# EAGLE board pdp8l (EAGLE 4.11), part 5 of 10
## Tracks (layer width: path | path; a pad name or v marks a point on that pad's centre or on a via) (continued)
MA05\  (via drill 0.61) (continued)
  Route15 0.203: v402.74,227.43 403.15,227.43 410.06,220.52 410.06,209.14 411.68,207.52 412.09,207.52 414.93,204.67 418.19,204.67 430.38,192.48 432,192.48 432.82,191.67 437.29,191.67 444.6,184.35 448.67,184.35 B01.H2 | v91.85,261.16 91.85,259.94 115.01,236.78 120.7,236.78 121.11,236.37 121.92,236.37 140.61,217.68 145.49,217.68 162.15,201.02 162.97,201.02 165.81,198.17 166.62,198.17 169.47,195.33 170.69,195.33 172.31,193.7 B23.D1 | v224.33,190.04 221.08,186.79 v222.71,185.17 | v366.57,276.2 397.87,244.91 401.12,244.91 AB05.AL1
  Bottom 0.203: v91.85,261.16 91.44,261.57 48.77,261.57 46.33,259.13 18.69,259.13 17.88,259.94 A35.E2 | v224.33,190.04 226.37,192.07 265.38,192.07 268.22,189.23 282.85,189.23 283.67,190.04 B14.E2 | v222.71,185.17 222.3,185.57 189.38,185.57 185.72,189.23 v173.53,189.23 | v366.57,276.2 366.17,276.61 357.23,276.61 356.41,277.42 334.87,277.42 333.25,275.79 317.4,275.79 316.99,275.39 306.02,275.39 304.39,277.01 286.92,277.01 286.51,276.61 255.63,276.61 254.81,277.42 242.21,277.42 v241.81,277.01
MA06  (via drill 0.61)
  Top 0.203: v219.46,122.58 216.21,125.83 v216.21,165.25 | v247.5,200.61 250.34,203.45 250.34,216.05 247.9,218.49 247.9,222.15 250.75,224.99 v250.75,257.91 | v321.87,268.88 323.49,270.51 323.49,274.57 v327.96,279.04 | v388.93,281.89 391.77,279.04 391.77,277.83 392.58,277.01 412.9,277.01 412.9,260.76 415.75,257.91 415.75,247.75 411.28,243.28 411.28,242.06 AB04.AM2
  Route2 0.203: v216.21,165.25 216.61,165.25 228.4,177.04 228.4,181.51 v247.5,200.61 | v314.15,261.16 v321.87,268.88 | v327.96,279.04 329.18,279.04 332.44,275.79 334.06,275.79 335.28,277.01 367.79,277.01 368.2,277.42 371.04,277.42 371.86,278.23 375.51,278.23 376.33,279.04 386.08,279.04 v388.93,281.89
  Bottom 0.203: v219.46,122.58 232.05,122.58 232.87,123.39 C18.E2 | v250.75,257.91 251.56,258.72 311.71,258.72 v314.15,261.16
MA06\  (via drill 0.61)
  Top 0.203: v412.09,172.97 412.5,173.38 412.5,205.89 410.06,208.33 410.06,212.8 410.46,213.21 410.46,214.83 412.09,214.83 415.75,218.49 415.75,239.62 416.97,240.84 AB04.AM1 | v219.05,172.97 219.05,126.24 220.68,124.61 C19.E2 | v282.85,172.57 282.85,185.17 281.23,186.79 B14.F2
  Route15 0.203: v64.21,279.04 104.85,238.4 105.26,238.4 113.79,229.87 113.79,229.46 114.2,229.06 115.01,229.06 151.18,192.89 151.18,192.07 167.84,175.41 167.84,173.79 169.47,172.16 B23.M2
  Bottom 0.203: B01.M2 448.67,171.75 447.45,172.97 v412.09,172.97 411.68,172.97 375.92,172.97 375.51,173.38 341.78,173.38 341.38,172.97 282.85,172.97 v282.85,172.57 282.45,172.97 219.46,172.97 v219.05,172.97 171.09,172.97 170.28,172.16 B23.M2 | v64.21,279.04 3.25,279.04 3.25,259.94 7.32,255.88 15.04,255.88 16.66,254.25 A35.H2
MA07  (via drill 0.61)
  Top 0.203: v360.88,244.91 358.44,247.34 358.44,260.35 355.19,263.6 355.19,270.1 352.35,272.95 v352.35,273.36 | v212.14,147.37 210.51,145.75 210.51,135.99 209.7,135.18 209.7,132.74 213.77,128.68 215.8,128.68 215.8,125.02 220.27,120.55 220.27,118.11 C19.H2
  Route2 0.203: v360.88,244.91 360.88,245.31 371.45,255.88 376.73,255.88 379.17,258.32 387.3,258.32 391.77,262.79 407.62,246.94 407.62,244.91 AB04.AL2 | v352.35,273.36 351.13,274.57 348.29,271.73 342.19,271.73 332.84,262.38 327.15,262.38 303.58,238.81 303.58,238.4 294.64,229.46 294.23,229.46 293.42,228.65 292.61,228.65 289.76,225.81 289.36,225.81 288.95,225.4 288.95,224.59 283.67,219.3 283.67,218.49 250.34,185.17 249.94,185.17 v212.14,147.37
  Bottom 0.203: C19.H2 221.08,116.89 221.89,116.08 232.05,116.08 232.87,116.89 C18.H2
MA07\  (via drill 0.61)
  Top 0.203: v287.32,273.76 279.6,266.04 279.6,262.38 279.2,261.98 279.2,257.1 278.38,256.29 278.38,255.47 279.2,254.66 279.2,230.28 v278.79,229.87
  Route15 0.203: B01.P2 449.48,165.66 449.48,169.72 451.1,171.35 451.1,186.38 444.6,192.89 444.6,205.89 425.91,224.59 425.91,230.28 422.66,233.53 422.66,234.34 416.15,240.84 416.15,242.06 414.53,243.69 AB04.AL1 413.71,244.91 411.28,244.91 387.3,268.88 385.67,268.88 383.24,271.32 378.76,271.32 372.26,277.83 371.45,277.83 369.01,275.39 v369.42,274.98 | A35.K2 17.88,248.16 17.88,252.22 23.98,258.32 19.51,262.79 19.51,270.92 33.33,284.73 60.96,284.73 169.06,176.63 170.69,176.63 172.31,175.01 B23.L1 | v278.79,229.87 278.79,229.46 279.2,229.06 279.2,218.08 293.83,203.45 293.83,201.83 295.05,200.61 295.05,196.14 v297.89,193.29
  Bottom 0.203: B23.L1 173.53,175.01 174.35,175.82 189.79,175.82 193.45,179.48 256.03,179.48 259.28,182.73 278.38,182.73 278.79,183.13 283.26,183.13 283.67,183.54 B14.H2 284.89,184.35 288.54,184.35 288.54,190.45 290.17,192.07 296.67,192.07 v297.89,193.29 | v369.42,274.98 369.01,275.39 365.76,275.39 364.95,276.2 356.82,276.2 356.01,277.01 335.28,277.01 333.65,275.39 317.81,275.39 317.4,274.98 288.54,274.98 v287.32,273.76
MA08  (via drill 0.61)
  Top 0.203: v314.55,278.23 314.55,265.23 313.33,264.01 A12.D1 | v423.06,276.2 422.66,275.79 422.66,242.88 423.47,242.06 AB03.AM2 | v202.39,119.33 202.79,119.74 202.79,179.88 201.98,180.7 201.98,182.32 203.2,183.54 v203.2,221.74
  Route2 0.203: v230.84,227.03 233.68,227.03 267.41,260.76 v267.41,261.16
  Bottom 0.203: C18.F2 229.62,120.14 228.8,119.33 219.46,119.33 218.24,120.55 C19.F2 217.02,120.14 216.21,119.33 v202.39,119.33 | v314.55,278.23 330.81,278.23 332.44,279.86 358.85,279.86 359.66,279.04 364.95,279.04 366.17,280.26 384.86,280.26 386.89,278.23 391.36,278.23 392.18,279.04 420.22,279.04 v423.06,276.2 | v203.2,221.74 203.2,227.03 v230.84,227.03 | v267.41,261.16 267.82,261.57 289.76,261.57 293.42,265.23 310.9,265.23 312.12,264.01 A12.D1
MA08\  (via drill 0.61)
  Top 0.203: v434.44,157.53 434.85,157.94 434.85,201.02 432.41,203.45 432.41,218.08 432,218.49 432,239.62 430.78,240.84 AB03.AM1
  Bottom 0.203: A35.M2 17.88,241.66 18.69,242.47 425.91,242.47 426.72,241.66 429.56,241.66 AB03.AM1 | v434.44,157.53 443.79,157.53 445.41,155.91 B01.T2
MA09  (via drill 0.61)
  Top 0.203: v185.32,55.12 190.19,55.12 190.19,213.21 v189.79,213.61
  Route2 0.203: v189.79,213.61 253.59,277.42 260.91,277.42 v264.57,281.08 | v362.92,259.54 363.73,259.54 378.76,274.57 382.42,274.57 v385.27,277.42
  Route15 0.203: v264.57,281.08 267.82,284.33 338.53,284.33 349.91,272.95 349.91,272.54 351.13,271.32 351.54,271.32 362.92,259.94 v362.92,259.54 | v385.27,277.42 385.67,277.42 391.36,271.73 391.77,271.73 392.18,271.32 392.18,270.92 416.97,246.13 419,246.13 420.22,244.91 AB03.AL2
  Bottom 0.203: v185.32,55.12 158.5,55.12 157.68,54.3 D24.E2
MA09\  (via drill 0.61)
  Top 0.203: v24.79,210.77 25.2,211.18 25.2,237.19 v23.57,238.81 | v177.6,12.45 171.91,18.14 171.91,60 170.28,61.62 168.66,61.62 168.66,55.52 169.47,54.71 D23.E2
  Route2 0.203: v23.57,238.81 23.16,238.81 21.13,236.78 19.1,236.78 17.88,235.56 A35.P2 | v358.85,12.45 359.26,12.85 361.7,12.85 403.96,55.12 405.59,55.12 406.81,56.34 406.81,57.96 414.12,65.28 418.19,65.28 420.22,67.31 420.22,69.75 429.56,79.1 429.56,80.72 433.22,84.38 433.22,86.41 451.1,104.29 451.1,114.86 455.17,118.92 455.17,123.39 C01.E1
  Route15 0.203: C01.E1 455.57,124.61 455.57,128.27 454.36,129.49 454.36,215.24 428.75,240.84 428.75,242.06 427.13,243.69 AB03.AL1 | v24.79,210.77 32.11,203.45 32.11,192.89 86.97,138.02 87.78,138.02 169.47,56.34 169.47,54.71 D23.E2 | v358.85,12.45 352.35,5.94 342.6,5.94 341.38,7.16 322.27,7.16 v314.15,15.29
  Bottom 0.203: v314.15,15.29 312.12,17.32 307.64,17.32 307.24,16.92 305.61,16.92 305.21,17.32 295.86,17.32 292.61,14.07 233.68,14.07 230.02,10.41 179.63,10.41 v177.6,12.45
MA10  (via drill 0.61)
  Top 0.203: v374.7,277.42 368.2,283.92 308.86,283.92 308.86,281.08 v303.99,276.2 | v167.84,210.77 168.25,210.36 168.25,124.21 162.15,118.11 162.15,79.1 164.59,76.66 164.59,69.75 158.5,63.65 158.5,49.02 157.68,48.21 D24.H2
  Route2 0.203: v277.98,275.39 274.32,279.04 273.91,278.64 264.97,278.64 262.53,276.2 259.69,276.2 216.21,232.72 216.21,230.68 215.8,230.28 213.77,230.28 203.2,219.71 203.2,219.3 202.79,218.9 200.35,218.9 199.14,217.68 196.29,217.68 194.67,216.05 193.85,216.05 v192.23,214.43
  Route15 0.203: v374.7,277.42 376.73,279.45 383.64,279.45 384.45,278.64 387.71,278.64 391.36,274.98 399.49,274.98 399.9,274.57 405.59,274.57 436.47,243.69 436.47,242.06 AB02.AM2
  Bottom 0.203: D24.H2 157.68,48.21 158.5,49.02 167.84,49.02 169.06,47.8 D23.H2 | v303.99,276.2 303.17,275.39 v277.98,275.39 | v192.23,214.43 188.57,210.77 v167.84,210.77
MA10\  (via drill 0.61)
  Top 0.203: v434.44,121.77 432.82,123.39 432.82,125.42 431.6,126.64 431.6,215.65 429.56,217.68 429.56,220.93 428.35,222.15 428.35,241.25 v427.13,242.47 | v74.37,283.92 30.07,283.92 26.01,279.86 26.01,272.54 18.69,265.23 18.69,229.87 17.88,229.06 A35.S2 | v254.41,268.88 254.41,274.57 261.72,281.89 261.72,283.11 281.23,283.11 281.23,279.86 281.63,279.45 294.23,279.45 v294.23,273.76 | v382.02,253.44 387.3,248.16 v387.3,244.91
  Route2 0.203: v74.37,283.92 105.66,283.92 106.88,282.7 107.7,283.52 165.41,283.52 v167.44,281.48 | v346.66,232.72 348.69,232.72 352.75,236.78 360.07,236.78 375.51,252.22 380.8,252.22 v382.02,253.44
  Route15 0.203: v167.44,281.48 235.71,281.48 245.47,271.73 251.56,271.73 v254.41,268.88 | v294.23,273.76 299.52,268.48 303.99,268.48 324.31,248.16 325.53,248.16 325.93,247.75 326.75,247.75 328.37,249.38 328.78,248.97 329.18,248.97 330,248.16 330,247.75 330.4,247.34 331.62,247.34 343.41,235.56 344.22,235.56 346.66,233.12 v346.66,232.72
  Bottom 0.203: v434.44,121.77 435.66,121.77 441.76,115.67 451.1,115.67 451.92,114.86 C01.J1 | AB02.AM1 442.16,241.66 441.35,242.47 v427.13,242.47 427.13,242.88 401.12,242.88 398.27,245.72 388.11,245.72 v387.3,244.91
MA11  (via drill 0.61)
  Top 0.203: v377.14,278.23 374.7,278.23 368.61,284.33 293.83,284.33 293.83,281.08 293.01,280.26 281.63,280.26 281.63,283.52 257.66,283.52 257.66,278.64 254.81,275.79 253.19,275.79 253.19,282.3 251.97,283.52 230.84,283.52 v230.84,278.64 | v222.71,279.04 183.69,279.04 183.69,253.03 180.85,250.19 180.85,185.98 180.44,185.57 180.44,181.91 180.85,181.51 180.85,130.3 171.5,120.95 171.5,65.28 167.84,61.62 167.84,52.27 167.03,51.46 D23.F2
  Route15 0.203: v377.14,278.23 377.55,278.64 383.64,278.64 384.05,278.23 385.67,278.23 389.33,274.57 399.08,274.57 400.71,272.95 402.74,272.95 430.78,244.91 432.82,244.91 AB02.AL2
  Bottom 0.203: D24.F2 154.43,51.46 155.25,52.27 165.41,52.27 166.22,51.46 D23.F2 | v230.84,278.64 230.02,279.45 223.11,279.45 v222.71,279.04
MA11\  (via drill 0.61)
  Top 0.203: v61.77,264.41 63.4,266.04 63.4,270.92 71.12,278.64 v103.63,278.64 | v426.72,272.54 438.51,260.76 438.51,245.72 | 438.51,245.72 439.32,244.91 AB02.AL1 | v438.1,200.61 438.51,201.02 438.51,245.72
  Route2 0.203: v61.77,264.41 44.7,247.34 44.7,246.53 21.13,222.96 17.88,222.96 A35.U2 | v277.17,263.2 277.98,263.2 289.76,274.98 292.61,274.98 293.01,275.39 299.11,275.39 306.02,282.3 306.83,282.3 307.24,281.89 307.24,281.08 312.93,275.39 v317.81,280.26 | v326.75,279.45 327.15,279.45 327.56,279.86 385.67,279.86 388.52,282.7 390.96,282.7 401.52,272.14 401.52,271.73 401.93,271.32 425.5,271.32 v426.72,272.54 | v438.1,200.61 437.29,199.8 453.95,183.13 453.95,148.59 452.32,146.96 452.32,141.68 451.51,140.87 451.51,140.06 451.1,139.65 451.1,116.48 450.7,116.08 450.7,110.39 446.23,105.92 446.23,102.26 C01.N2
  Route15 0.203: v103.63,278.64 113.39,278.64 118.67,283.92 245.87,283.92 258.06,271.73 268.63,271.73 v277.17,263.2
  Bottom 0.203: v317.81,280.26 318.21,280.67 325.53,280.67 v326.75,279.45
MA_ENABLE(0-4)  (via drill 0.61)
  Top 0.203: AB07.BP1 379.98,164.85 382.02,162.81 382.02,162.41 AB06.BR2 | v392.58,243.69 392.99,243.28 392.99,242.47 393.39,242.06 393.39,166.47 392.58,165.66 AB06.BP1
  Route15 0.203: v359.66,244.91 357.63,246.94 357.63,250.19 A08.J2
  Bottom 0.203: AB07.BR2 370.64,162 371.86,163.22 377.55,163.22 378.36,162.41 382.02,162.41 AB06.BR2 | 390.14,166.47 391.36,165.25 AB06.BP1 | 390.14,166.47 382.42,166.47 381.2,165.25 379.98,165.25 AB07.BP1 | 390.14,166.47 399.08,166.47 400.3,165.25 404.37,165.25 AB05.BP1 | v359.66,244.91 361.29,243.28 392.18,243.28 v392.58,243.69
MA_ENABLE(5-11)  (via drill 0.61)
  Top 0.203: AB03.BR2 420.22,162.41 418.19,164.44 418.19,164.85 AB04.BP1 | v346.25,244.5 346.25,248.56 344.63,250.19 A09.J2 | v393.8,243.28 393.8,163.22 394.61,162.41 AB05.BR2
  Bottom 0.203: AB02.BP1 442.16,165.25 440.94,166.47 431.6,166.47 430.78,165.66 AB03.BP1 429.56,165.25 428.35,166.47 419.4,166.47 418.19,165.25 AB04.BP1 | AB02.BR2 432.82,162.41 432,163.22 422.66,163.22 421.44,162 AB03.BR2 420.22,161.59 419.4,160.78 406.4,160.78 | 406.4,160.78 396.65,160.78 395.83,161.59 AB05.BR2 | 406.4,160.78 407.21,161.59 AB04.BR2 | v346.25,244.5 347.88,242.88 393.39,242.88 v393.8,243.28
MA_LOAD  (via drill 0.61)
  Top 0.203: v366.98,176.22 368.2,175.01 368.2,160.78 366.98,159.56 B08.S1 | v390.14,203.86 390.14,220.52 387.71,222.96 387.71,232.72 390.55,235.56 390.55,245.72 391.77,246.94 AB06.AK1
  Route2 0.203: v366.98,176.22 367.39,176.22 390.14,198.98 v390.14,203.86
  Bottom 0.203: AB02.AK1 442.16,247.75 440.94,248.97 431.6,248.97 430.78,248.16 AB03.AK1 429.56,248.16 428.75,248.97 422.25,248.97 421.03,247.75 418.19,247.75 AB04.AK1 416.97,248.16 416.15,248.97 403.56,248.97 | 390.14,248.97 380.8,248.97 379.98,248.16 AB07.AK1 | 390.14,248.97 391.36,247.75 AB06.AK1 | 403.56,248.97 404.37,248.16 AB05.AK1 | 390.14,248.97 403.56,248.97
MANUAL_PRESET\  (via drill 0.61)
  Top 0.203: v386.89,112.42 387.3,112.01 387.3,87.63 386.08,86.41 C06.U2 | v416.15,114.05 416.15,124.61 414.53,126.24 C04.D1 | v334.06,52.68 336.09,50.65 336.09,42.11 335.69,41.71 D10.K2 | B11.K1 328.37,177.04 328.37,174.6 327.15,173.38 327.15,170.94 330,168.1 330,151.03 v329.18,150.22 328.78,150.22 328.78,146.15 330,144.93 330,129.49 329.59,129.08 329.59,125.42 330,125.02 330,122.58 | 330,122.58 330,96.98 327.15,94.13 327.15,85.19 327.96,84.38 327.96,73.81 330,71.78 330,55.93 328.78,54.71 D11.E1 | v329.59,122.58 330,122.58
  Route2 0.203: B08.E1 366.17,190.04 361.7,190.04 355.19,183.54 355.19,183.13 348.29,176.22 347.88,176.22 341.78,170.13 337.72,170.13 327.15,159.56 327.15,158.34 326.75,157.94 325.93,157.94 324.31,156.31 324.31,154.69 322.68,153.06 B11.U2
  Route15 0.203: v351.94,123.39 360.07,115.27 360.07,111.61 C08.K2
  Bottom 0.203: 386.89,112.83 399.49,112.83 399.9,112.42 409.25,112.42 410.46,111.2 C04.K2 411.68,111.61 413.71,111.61 v416.15,114.05 | 386.89,112.83 377.55,112.83 377.14,112.42 361.7,112.42 360.88,111.61 C08.K2 | 386.89,112.83 v386.89,112.42 | v334.06,52.68 333.65,53.09 329.59,53.09 329.18,53.49 D11.E1 | v329.18,150.22 328.78,150.62 323.9,150.62 322.68,151.84 B11.U2 | v351.94,123.39 349.1,123.39 348.29,122.58 v329.59,122.58
MB00  (via drill 0.61)
  Top 0.203: v277.98,220.52 v277.98,205.08
  Route2 0.203: v229.62,190.86 214.58,175.82 214.58,173.38 214.17,172.97 213.77,172.97 178,137.21 178,135.59 123.95,81.53 123.95,80.72 112.98,69.75 112.98,67.31 D28.A1 | v308.46,251 308.46,250.6 293.83,235.97 293.83,234.75 288.54,229.46 286.92,229.46 v277.98,220.52 | v277.98,205.08 277.57,205.08 267,194.51 267,192.89 265.38,191.26 B16.E1
  Route15 0.203: v340.97,251.82 366.98,225.81 369.42,225.81 AB07.AT2
  Bottom 0.203: v229.62,190.86 230.43,191.67 263.75,191.67 264.57,190.86 B16.E1 | v340.97,251.82 340.56,252.22 311.3,252.22 310.08,251 v308.46,251
MB00\  (via drill 0.61)
  Top 0.203: v373.48,188.82 374.29,189.64 374.29,205.49 372.26,207.52 372.26,221.34 372.67,221.74 AB07.AU2
  Route2 0.203: v386.08,186.38 402.34,202.64 402.34,205.49 412.09,215.24 412.9,215.24 414.12,216.46 415.34,216.46 426.72,227.84 427.53,227.84 445.41,245.72 447.04,245.72 448.67,247.34 A01.K2 | v373.07,227.03 373.07,222.96 AB07.AU2 | v310.49,252.63 310.49,251.82 295.05,236.37 295.05,235.56 294.23,234.75 294.23,234.34 282.85,222.96 282.85,218.9 281.63,217.68 280.01,217.68 265.79,203.45 B16.A1
  Route15 0.203: B16.A1 264.57,203.45 262.53,203.45 228.4,237.59 225.96,237.59 220.27,231.9 218.64,233.53 211.33,233.53 199.14,245.72 193.85,245.72 177.6,261.98 176.38,261.98 173.53,264.82 168.66,264.82 167.44,263.6 A23.D2 | v373.07,227.03 372.67,227.03 v347.88,251.82
  Bottom 0.203: v373.48,188.82 373.48,186.79 374.7,186.79 375.51,185.98 385.67,185.98 v386.08,186.38 | v347.88,251.82 347.47,252.22 341.78,252.22 341.38,252.63 v310.49,252.63
MB01  (via drill 0.61)
  Route2 0.203: v245.87,186.79 197.1,138.02 194.67,138.02 179.22,122.58 178.41,122.58 174.75,118.92 168.66,118.92 119.89,70.16 118.67,70.16 112.57,64.06 110.13,64.06 D28.B1 | v361.7,227.43 360.88,227.43 357.63,224.18 353.97,224.18 351.94,222.15 v351.94,221.74 | v340.16,223.37 340.16,222.96 336.91,219.71 336.91,218.08 v329.18,210.36 | v309.27,227.03 309.27,226.62 304.39,221.74 304.39,221.34 300.74,217.68 295.45,217.68 v265.79,188.01
  Route15 0.203: v329.18,210.36 328.37,211.18 326.34,211.18 324.31,213.21 323.09,213.21 v309.27,227.03
  Bottom 0.203: v245.87,186.79 247.9,188.82 260.1,188.82 261.31,187.6 B16.F1 262.53,187.6 265.38,187.6 v265.79,188.01 | v361.7,227.43 367.39,227.43 367.79,227.84 371.86,227.84 372.26,228.24 AB07.AS2 | v351.94,221.74 350.72,222.96 349.1,222.96 348.29,223.77 340.56,223.77 v340.16,223.37
MB01\  (via drill 0.61)
  Top 0.203: v378.76,232.72 379.58,231.9 379.58,229.06 AB07.AS1 | v416.15,277.01 416.15,253.44 420.62,248.97 v420.62,248.56 | v171.91,280.26 171.91,264.82 172.72,264.01 A23.D1
  Route2 0.203: v408.84,236.78 409.25,236.78 420.62,248.16 v420.62,248.56
  Route15 0.203: B16.B1 261.72,200.61 261.72,203.45 252.37,212.8 251.16,212.8 243.43,220.52 238.56,220.52 237.74,221.34 236.12,221.34 233.68,223.77 227.58,223.77 218.24,233.12 205.64,233.12 177.19,261.57 175.16,261.57 173.53,263.2 A23.D1
  Bottom 0.203: v378.76,232.72 379.58,233.53 382.42,233.53 385.27,236.37 390.55,236.37 390.96,236.78 400.3,236.78 400.71,236.37 403.15,236.37 403.56,236.78 v408.84,236.78 | v420.62,248.56 421.44,249.38 449.07,249.38 453.14,253.44 455.17,253.44 A01.H1 | v416.15,277.01 415.34,277.83 393.39,277.83 392.99,277.42 386.49,277.42 384.05,279.86 366.57,279.86 365.35,278.64 359.26,278.64 358.44,279.45 332.84,279.45 331.22,277.83 315.37,277.83 314.96,277.42 313.74,277.42 311.71,279.45 273.91,279.45 273.51,279.04 238.15,279.04 236.53,280.67 172.31,280.67 v171.91,280.26
MB02  (via drill 0.61)
  Top 0.203: v378.36,250.6 380.8,248.16 380.8,238 382.02,236.78 382.02,234.75 381.2,233.93 381.2,231.09 381.61,230.68 381.61,227.03 382.42,226.21 AB06.AT2 | v368.61,276.61 v368.61,260.35 | v235.31,278.23 235.31,266.85 237.74,264.41 237.74,220.93 v237.34,220.52
  Route2 0.203: D28.F1 110.13,51.05 113.39,51.05 141.83,79.5 159.31,79.5 215.8,135.99 215.8,138.43 252.78,175.41 252.78,175.82 253.19,176.22 255.63,176.22 257.25,177.85 257.25,178.26 261.31,182.32 263.35,182.32 264.57,183.54 B16.H1
  Route15 0.203: v368.61,260.35 v378.36,250.6 | v237.34,220.52 237.74,220.12 237.74,213.21 246.28,204.67 246.69,204.67 264.16,187.2 264.16,186.79 264.57,186.38 264.57,184.76 B16.H1
  Bottom 0.203: v368.61,276.61 367.79,277.42 358.04,277.42 357.23,278.23 334.06,278.23 332.44,276.61 316.59,276.61 316.18,276.2 310.49,276.2 308.46,278.23 286.51,278.23 285.7,277.42 256.44,277.42 255.63,278.23 v235.31,278.23
MB02\  (via drill 0.61)
  Top 0.203: v387.3,233.53 387.3,224.18 386.08,222.96 AB06.AU2 | v263.35,205.08 263.35,198.58 264.57,197.36 B16.C1 | v167.84,215.65 167.84,238.81 169.47,240.44 169.47,240.84 A23.M2 169.88,242.06 169.88,244.09 171.09,245.31 v171.09,279.04
  Route15 0.203: v407.62,235.56 407.62,236.37 403.56,240.44 403.56,242.88 403.15,243.28 403.15,244.91 402.34,245.72 397.87,245.72 384.45,259.13 384.45,264.41 v371.86,277.01
  Bottom 0.203: 407.62,233.53 439.32,233.53 443.79,238 445.41,238 A01.N2 | 407.62,233.53 v387.3,233.53 | v263.35,205.08 262.53,205.89 249.53,205.89 249.12,205.49 236.12,205.49 235.31,206.3 206.45,206.3 197.1,215.65 v167.84,215.65 | v407.62,235.56 407.62,233.53 | v371.86,277.01 371.04,277.83 358.44,277.83 357.63,278.64 333.65,278.64 332.03,277.01 316.18,277.01 315.77,276.61 310.9,276.61 308.86,278.64 286.11,278.64 285.29,277.83 256.85,277.83 256.03,278.64 237.74,278.64 236.12,280.26 173.13,280.26 171.91,279.04 v171.09,279.04
MB03  (via drill 0.61)
  Top 0.203: v391.77,219.71 391.36,219.3 391.36,211.99 391.77,211.58 391.77,205.08 390.96,204.27 390.96,193.7 v391.36,193.29 | v271.48,167.69 270.66,168.5 270.66,170.13 270.26,170.54 270.26,181.51 v270.66,181.91 | v345.85,81.53 345.85,83.16 344.63,84.38 344.63,85.6 345.85,86.82 345.85,89.66 345.44,90.07 345.44,93.73 344.63,94.54 C09.R2
  Route2 0.203: v391.36,193.29 391.36,192.89 v364.13,165.66 | v373.48,155.5 373.48,154.69 368.61,149.81 368.61,148.18 358.85,138.43 358.85,137.21 356.01,134.37 356.01,129.9 349.5,123.39 349.5,122.17 345.03,117.7 344.22,117.7 342.19,115.67 341.38,115.67 334.47,108.76 332.84,108.76 332.44,108.36 C10.L2 | v271.48,167.69 241.81,138.02 239.37,138.02 236.12,134.77 235.31,134.77 v233.27,132.74 184.51,83.97 178.82,83.97 131.27,36.42 118.67,36.42 117.45,35.2 113.39,35.2 D28.M1
  Route15 0.203: C09.R2 343.81,95.35 342.19,95.35 333.65,103.89 333.65,105.51 332.03,107.14 C10.L2 | v391.77,219.71 388.93,222.56 388.11,222.56 386.08,224.59 386.08,227.84 AB06.AS2 | v364.13,165.66 364.13,164.85 v373.48,155.5 | v284.48,82.35 284.07,82.35 259.28,107.14 259.28,107.54 254.81,112.01 254.41,112.01 233.68,132.74 v233.27,132.74
  Bottom 0.203: v270.66,181.91 270.26,182.32 263.35,182.32 262.53,181.51 B16.J1 | v345.85,81.53 345.03,80.72 286.11,80.72 v284.48,82.35
MB03\  (via drill 0.61)
  Top 0.203: D28.H1 112.98,48.21 114.61,49.84 v114.61,125.02 114.61,125.42 110.95,129.08 v110.95,192.89 | v66.24,194.92 66.24,188.82 65.43,188.01 AB31.BF2 | v42.27,249.78 44.7,249.78 44.7,215.65 47.14,213.21 47.14,207.52 44.7,205.08 44.7,196.54 v45.52,195.73 | v327.15,124.61 327.15,112.42 327.96,111.61 C11.K1 | B15.H2 271.07,183.54 269.85,182.32 269.85,170.54 268.63,169.32 268.63,168.91 B15.N2 268.63,167.69 269.44,166.88 v269.44,125.83 | v171.91,195.33 171.91,242.88 172.72,243.69 A23.L1 | v263.75,185.98 263.35,186.38 263.35,189.64 262.13,190.86 262.13,192.89 B16.D1 | v390.96,211.18 390.96,222.96 391.36,223.37 391.36,227.43 391.77,227.84 AB06.AS1 | v288.54,206.7 288.54,169.72 287.73,168.91 B14.N1
  Route15 0.203: v392.58,230.68 392.58,229.06 AB06.AS1
  Bottom 0.203: 66.24,125.02 54.46,125.02 52.83,126.64 C32.D2 | 66.24,125.02 67.46,123.8 C31.E2 | v114.61,125.02 66.24,125.02 | v42.27,249.78 41.86,249.38 19.91,249.38 17.07,252.22 10.16,252.22 4.06,258.32 1.63,258.32 1.63,262.79 A36.D2 | v45.52,195.73 46.33,194.92 65.84,194.92 v66.24,194.92 76.4,194.92 77.22,194.11 AB30.BD2 78.44,193.29 79.25,192.48 110.54,192.48 v110.95,192.89 111.35,192.89 113.79,195.33 154.84,195.33 155.25,194.92 171.91,194.92 v171.91,195.33 172.31,194.92 260.5,194.92 261.31,194.11 B16.D1 | v392.58,230.68 392.99,230.28 444.19,230.28 445.41,231.5 A01.R2 | C10.E2 334.47,124.21 331.62,124.21 330.81,125.02 327.56,125.02 v327.15,124.61 327.15,125.02 302.36,125.02 300.74,126.64 C13.D1 299.52,126.64 298.7,125.83 v269.44,125.83 | B15.N2 269.04,168.1 270.26,166.88 286.11,166.88 286.92,167.69 B14.N1 | v263.75,185.98 264.16,185.57 269.44,185.57 270.66,184.35 B15.H2 | v390.96,211.18 386.49,206.7 353.57,206.7 353.16,206.3 315.77,206.3 315.37,205.89 306.02,205.89 305.61,206.3 302.77,206.3 302.36,206.7 v288.54,206.7
MB04  (via drill 0.61)
  Top 0.203: v346.66,56.34 346.25,55.93 346.25,46.99 349.1,44.15 349.1,18.95 349.91,18.14 349.91,13.66 350.32,13.26 D09.V1 | v404.77,115.27 405.99,116.48 405.99,117.7 406.4,118.11 406.4,155.5 403.15,158.75 403.15,214.02 399.9,217.27 399.9,223.77 397.05,223.77 395.83,224.99 AB05.AT2 | v276.35,118.52 v276.35,128.27
  Route2 0.203: v151.18,58.78 174.35,81.94 174.35,92.91 217.83,136.4 218.64,136.4 220.27,138.02 221.08,138.02 239.78,156.72 239.78,157.12 243.43,160.78 243.84,160.78 244.25,161.19 244.25,162.81 245.87,164.44 B17.P2 | v404.77,115.27 380.39,90.88 380.39,89.66 378.76,88.04 378.76,87.22 375.11,83.57 375.11,80.72 367.79,73.41 367.79,72.19 360.88,65.28 356.01,65.28 347.07,56.34 v346.66,56.34
  Route15 0.203: v346.66,56.34 346.66,58.37 322.68,82.35 321.46,82.35 305.21,98.6 305.21,101.85 304.8,102.26 302.77,102.26 302.36,102.67 302.36,103.89 301.14,105.1 301.14,107.14 303.17,109.17 v294.23,118.11 | v276.35,128.27 272.69,131.93 272.69,137.21 263.35,146.56 263.35,149.81 253.19,159.97 252.78,159.97 252.37,160.38 252.37,160.78 248.31,164.85 246.69,164.85 B17.P2
  Bottom 0.203: v151.18,58.78 141.02,58.78 138.18,55.93 104.44,55.93 103.63,56.74 D28.D2 | v294.23,118.11 295.05,118.92 | 295.05,118.92 314.15,118.92 315.37,117.7 C12.H1 | v276.35,118.52 276.76,118.92 295.05,118.92
MB04\  (via drill 0.61)
  Top 0.203: v104.85,122.58 104.85,90.88 | 104.85,90.88 104.85,73 108.1,69.75 108.1,33.58 109.32,32.36 D28.N1 | v6.5,248.16 6.5,257.91 4.88,259.54 A36.E2 | v70.31,246.53 69.9,246.13 69.9,220.52 69.09,219.71 69.09,204.27 70.31,203.05 70.31,194.51 70.71,194.11 AB31.BD1 | v76.4,192.07 76.4,126.24 74.78,124.61 C31.E1 | v269.04,176.22 269.44,176.63 269.44,185.98 268.63,186.79 B15.F2 | v333.25,49.02 333.25,116.48 v332.44,117.3 | v290.98,160.78 290.98,164.44 B14.P1 | v395.83,214.83 396.65,215.65 396.65,220.52 397.87,221.74 AB05.AU2 | v376.33,214.43 375.51,213.61 375.51,201.42 374.7,200.61 374.7,164.44 v375.11,164.03 | 104.85,90.88 v110.13,90.88
  Route2 0.203: v264.16,193.7 255.22,184.76 254,184.76 253.59,184.35 253.59,183.13 248.72,178.26 246.69,178.26 B17.K2 | v375.11,164.03 375.11,163.63 362.92,151.44 362.92,150.62 350.32,138.02 350.32,137.62 349.1,136.4 349.1,135.99 334.47,121.36 334.06,121.36 333.65,120.95 333.65,118.92 332.44,117.7 v332.44,117.3 | v110.13,90.88 114.61,90.88 115.01,91.29 116.64,91.29 118.67,93.32 123.95,93.32 139.8,109.17 139.8,109.98 177.19,147.37 180.85,147.37 v210.92,177.44
  Route15 0.203: D09.S1 354.79,22.61 356.82,22.61 363.73,29.52 349.5,43.74 349.5,45.36 347.88,46.99 D09.H2 | v264.16,193.7 264.16,193.29 266.6,190.86 266.6,189.23 267.82,188.01 B15.F2 | v269.04,176.22 271.07,174.19 271.07,172.16 B15.M2 | v332.44,117.3 310.9,138.84 310.9,140.87 v290.98,160.78
  Bottom 0.203: 73.15,122.58 63.4,122.58 62.59,123.39 C32.E1 | 73.15,122.58 73.97,123.39 C31.E1 | v104.85,122.58 104.85,124.61 102.82,124.61 100.79,122.58 73.15,122.58 | 76.4,191.67 79.65,191.67 80.47,190.86 AB30.BE2 | 76.4,191.67 73.56,191.67 71.93,193.29 AB31.BD1 | v6.5,248.16 8.53,246.13 69.9,246.13 v70.31,246.53 | 76.4,191.67 v76.4,192.07 | AB05.AU2 399.08,222.56 400.71,224.18 444.6,224.18 445.41,224.99 A01.T2 | B14.P1 290.98,165.66 292.2,166.88 294.23,166.88 295.05,167.69 295.05,170.13 276.35,170.13 275.54,170.94 271.88,170.94 B15.M2 | v333.25,49.02 345.85,49.02 347.07,47.8 D09.H2 | v395.83,214.83 395.43,215.24 377.14,215.24 v376.33,214.43 | v210.92,177.44 212.55,179.07 244.65,179.07 245.47,178.26 B17.K2
MB05  (via drill 0.61)
  Top 0.203: v244.65,173.79 244.65,163.63 243.43,162.41 B17.R2 243.03,161.19 244.65,159.56 244.65,151.84 v246.69,149.81 | v272.69,175.41 272.69,189.23 271.88,190.04 B15.E2 271.48,191.26 273.1,192.89 v273.1,215.65 | v104.85,67.72 104.85,42.52 105.66,41.71 D28.K2 | v289.36,69.34 289.36,103.48 290.17,104.29 C14.M1 | v2.44,195.33 2.85,195.73 2.85,201.02 2.44,201.42 2.44,217.27 2.85,217.68 2.85,244.91 2.44,245.31 2.44,249.78 2.85,250.19 2.85,255.88 2.03,256.69 A36.F2
  Route2 0.203: v397.05,225.4 398.27,226.62 398.27,227.84 AB05.AS2 | v322.68,227.03 313.33,217.68 309.27,217.68 306.43,214.83 305.21,214.83 303.58,213.21 302.77,213.21 300.33,215.65 v299.92,215.65
  Route15 0.203: v299.92,215.65 299.92,218.49 A13.V1 | v356.41,223.37 356.01,223.37 v351.94,227.43 | v2.44,195.33 2.44,194.51 2.85,194.11 2.85,188.82 16.66,175.01 16.66,174.19 41.05,149.81 41.05,147.37 102.01,86.41 103.63,86.41 111.76,78.28 112.17,78.28 113.79,76.66 113.79,69.75 v115.42,68.12 | v246.69,149.81 246.69,149.4 253.19,142.9 254.81,142.9 287.32,110.39 287.32,109.58 288.54,108.36 288.54,107.14 290.17,105.51 C14.M1
  Bottom 0.203: v244.65,173.79 246.69,175.82 252.78,175.82 253.19,176.22 266.19,176.22 267.41,175.01 267.82,175.01 B15.L2 269.04,175.01 272.29,175.01 v272.69,175.41 | v299.92,215.65 v273.1,215.65 | v397.05,225.4 395.83,224.18 358.44,224.18 357.63,223.37 v356.41,223.37 | v351.94,227.43 345.44,227.43 345.03,227.84 342.6,227.84 342.19,227.43 332.84,227.43 332.44,227.84 330,227.84 329.18,227.03 v322.68,227.03 | v104.85,67.72 105.66,68.53 115.42,68.53 | 115.42,68.53 170.69,68.53 171.5,69.34 v289.36,69.34 | 115.42,68.53 v115.42,68.12
MB05\  (via drill 0.61)
  Top 0.203: v102.01,80.31 102.01,75.03 107.7,69.34 107.7,55.93 106.48,54.71 D28.E2 | v68.28,80.31 66.65,81.94 66.65,115.67 65.02,117.3 65.02,120.14 C31.F2 65.02,121.36 63.8,122.58 63.8,177.04 v65.43,178.66 | v254,217.27 254.81,216.46 v254.81,204.27 | v241.81,203.05 244.25,200.61 244.25,178.26 243.03,177.04 243.03,175.41 B17.L2
  Route2 0.203: v65.43,178.66 67.06,180.29 67.06,185.17 68.28,186.38 65.43,189.23 65.43,192.89 AB31.BD2 | B17.L2 242.21,174.19 242.21,171.75 218.24,147.78 214.99,147.78 164.19,96.98 152.4,96.98 125.98,70.56 125.17,70.56 110.54,55.93 108.51,55.93 106.88,54.3 D28.E2 | v296.27,218.49 303.17,225.4 303.17,227.84 A13.S1
  Route15 0.203: B01.F2 445.41,187.6 443.79,187.6 418.19,213.21 418.19,213.61 414.12,217.68 413.71,217.68 406.81,224.59 406.81,226.21 405.18,227.84 AB05.AS1 | v253.19,160.78 245.06,168.91 245.06,170.54 244.65,170.94 244.65,171.75 243.43,172.97 243.43,174.19 B17.L2
  Bottom 0.203: A13.S1 303.99,228.65 304.8,229.46 308.46,229.46 308.86,229.87 399.49,229.87 400.71,228.65 404.37,228.65 AB05.AS1 | v253.19,160.78 284.07,160.78 284.48,161.19 286.92,161.19 B14.R1 | AB30.BE1 86.56,190.45 85.34,189.23 71.53,189.23 67.46,193.29 65.84,193.29 AB31.BD2 | C32.F1 59.33,120.14 64.62,120.14 C31.F2 | v68.28,80.31 v102.01,80.31 | v296.27,218.49 295.45,217.68 287.73,217.68 286.92,216.86 275.13,216.86 274.73,217.27 v254,217.27 | v254.81,204.27 254.41,204.67 243.43,204.67 v241.81,203.05
MB06  (via drill 0.61)
  Top 0.203: v284.89,160.38 285.29,160.78 285.29,175.41 286.11,176.22 v286.11,177.04 285.7,177.04 285.7,186.38 282.85,189.23 282.85,212.39 v283.26,212.8 | 288.54,255.88 287.73,256.69 A14.F1 | 288.54,255.88 288.54,249.78 287.73,248.97 282.85,248.97 282.85,244.5 286.11,241.25 286.11,218.49 285.7,218.08 285.7,216.46 286.92,215.24 v286.92,213.21 | v408.03,276.2 408.03,273.36 409.65,271.73 409.65,255.07 409.25,254.66 409.25,240.44 409.65,240.03 409.65,231.5 408.84,230.68 408.84,227.03 408.03,226.21 AB04.AT2 | v284.89,278.64 288.54,274.98 288.54,255.88 | v75.18,24.64 72.75,27.08 72.75,68.94 71.53,70.16 71.53,80.72 72.75,81.94 72.75,104.7 70.31,107.14 70.31,110.39 73.15,113.23 73.15,118.92 71.93,120.14 C31.F1 | v353.97,4.32 353.97,15.29 D09.U1 | v104.04,4.72 104.44,5.13 104.44,23.42 103.23,24.64 D28.R2 | v236.53,151.44 234.9,149.81 234.9,5.94 v234.09,5.13
  Route2 0.203: v236.53,151.44 243.43,158.34 245.47,158.34 B17.S2
  Bottom 0.203: v284.89,160.38 284.48,159.97 247.5,159.97 246.69,159.16 B17.S2 | v286.11,177.04 289.76,180.7 293.01,180.7 B13.J2 | v286.92,213.21 286.51,212.8 v283.26,212.8 | v408.03,276.2 407.21,277.01 386.08,277.01 385.67,276.61 373.48,276.61 371.86,278.23 358.85,278.23 358.04,279.04 333.25,279.04 331.62,277.42 315.77,277.42 315.37,277.01 311.3,277.01 309.27,279.04 285.29,279.04 v284.89,278.64 | v75.18,24.64 75.59,24.23 101.6,24.23 102.41,25.04 D28.R2 | v353.97,4.32 353.57,3.91 345.85,3.91 344.22,2.29 300.33,2.29 297.89,4.72 295.86,4.72 295.45,4.32 294.23,4.32 293.42,3.5 260.91,3.5 259.69,4.72 249.12,4.72 248.31,3.91 234.09,3.91 | 234.09,3.91 219.86,3.91 218.64,5.13 182.07,5.13 181.66,4.72 v104.04,4.72 | 234.09,3.91 v234.09,5.13
MB06\  (via drill 0.61)
  Top 0.203: v3.25,216.86 3.25,248.16 4.06,248.97 4.06,253.03 4.47,253.44 A36.H2 | v408.43,184.76 409.25,185.57 409.25,190.04 v406.81,192.48 406.81,222.15 409.25,224.59 409.25,228.65 410.46,229.87 412.5,229.87 412.5,224.18 411.28,222.96 AB04.AU2 | v247.09,176.63 247.09,172.97 246.28,172.16 B17.M2 245.47,170.94 v245.47,166.88 | v272.69,163.22 272.69,174.19 271.48,175.41 271.48,177.04 B15.K2 | v267,176.63 267,191.67 268.22,192.89 B15.D2 268.63,194.11 269.44,194.92 269.44,205.49 v269.85,205.89 | v96.32,85.6 98.35,83.57 98.35,38.86 98.75,38.46 102.41,38.46 D28.L2 103.63,37.64 104.85,36.42 v104.85,1.47 | v346.66,2.69 346.66,14.48 347.47,15.29 D09.U2 | v302.77,210.36 303.58,209.55 v303.58,205.08 | v66.24,185.57 66.65,185.17 66.65,118.52 v65.84,117.7
  Route2 0.203: v84.53,204.67 84.53,202.64 76.4,194.51 76.4,193.29 74.37,191.26 AB31.BE1 | v245.47,166.88 245.47,166.47 228.8,149.81 228.8,148.18 159.72,79.1 142.24,79.1 104.85,41.71 104.85,40.49 103.23,38.86 D28.L2
  Route15 0.203: AB31.BE1 75.18,190.04 75.59,190.04 77.62,188.01 AB30.BF2 | v96.32,85.6 64.62,117.3 62.59,117.3 C32.H1 | v355.6,192.89 355.19,192.89 340.56,207.52 v340.56,207.92 | v321.46,209.96 318.21,209.96 312.52,204.27 310.08,206.7 306.43,206.7 v302.77,210.36
  Bottom 0.203: v3.25,216.86 4.47,215.65 10.97,215.65 17.88,208.74 38.2,208.74 40.64,206.3 45.92,206.3 46.33,206.7 55.27,206.7 57.3,204.67 v84.53,204.67 | v408.43,184.76 410.46,182.73 433.63,182.73 436.88,179.48 445.82,179.48 445.82,175.41 B01.L2 | v247.09,176.63 v267,176.63 267.82,176.63 268.63,177.44 270.66,177.44 B15.K2 | v272.69,163.22 279.6,163.22 280.42,162.41 B14.R2 | v346.66,2.69 345.03,1.07 105.26,1.07 v104.85,1.47 | v406.81,192.48 356.01,192.48 v355.6,192.89 | v340.56,207.92 338.94,209.55 321.87,209.55 v321.46,209.96 | v303.58,205.08 279.2,205.08 278.38,205.89 v269.85,205.89 | v66.24,185.57 76,185.57 77.22,186.79 AB30.BF2 | v65.84,117.7 62.59,117.7 C32.H1
MB07  (via drill 0.61)
  Top 0.203: v57.3,141.68 56.9,141.28 56.9,118.92 56.08,118.11 C32.H2 | v69.49,143.31 69.49,189.23 68.68,190.04 AB31.BE2 | v124.77,143.31 124.77,137.62 125.17,137.21 C27.A1 | v242.62,131.52 243.03,131.52 244.25,132.74 244.25,154.28 243.43,155.09 B17.T2 | v265.38,145.75 264.57,144.93 264.57,138.02 263.75,137.21 263.75,126.24 263.35,125.83 v262.94,125.83 | v291.8,218.9 291.39,218.49 291.39,216.86 | 291.39,216.86 291.39,206.3 295.05,202.64 295.05,190.45 v294.64,190.04 | v299.52,185.17 299.52,181.51 B13.J1 | v409.25,215.65 409.65,216.05 409.65,226.62 410.87,227.84 AB04.AS2 | v356.41,215.65 355.6,216.46 v355.6,218.9 | 291.39,216.86 v291.8,216.86
  Route2 0.203: v265.38,145.75 267.41,147.78 269.04,147.78 286.11,164.85 286.11,168.91 287.73,170.54 287.73,170.94 297.49,180.7 299.52,180.7 B13.J1 | v291.8,218.9 291.8,219.3 294.23,221.74 296.27,221.74 A13.U2
  Route15 0.203: v262.94,125.83 263.75,125.02 263.75,122.99 281.63,105.1 283.67,105.1 C14.M2 | v299.52,185.17 v294.64,190.04
  Bottom 0.203: v57.3,141.68 67.87,141.68 68.68,142.49 | 68.68,142.49 v69.49,143.31 | v124.77,143.31 103.63,143.31 102.82,142.49 68.68,142.49 | v242.62,131.52 239.37,134.77 214.58,134.77 214.17,134.37 | 214.17,134.37 211.73,131.93 165,131.93 162.15,134.77 127.2,134.77 125.98,135.99 C27.A1 | v262.94,125.83 246.28,125.83 242.62,129.49 241,129.49 240.18,128.68 219.86,128.68 214.17,134.37 | v409.25,215.65 366.98,215.65 366.57,216.05 356.82,216.05 v356.41,215.65 | v355.6,218.9 353.97,220.52 341.78,220.52 338.53,217.27 292.2,217.27 v291.8,216.86
MB07\  (via drill 0.61)
  Top 0.203: v425.09,170.13 v425.09,227.43 | v278.79,168.1 279.2,168.5 279.2,172.16 277.98,173.38 277.98,177.04 B15.K1 | 273.51,192.07 274.32,192.89 B15.D1 | v273.51,178.66 273.51,192.07 | v274.32,216.46 273.91,216.05 273.91,201.42 273.51,201.02 273.51,192.07 | v82.91,138.43 82.91,185.98 83.72,186.79 AB30.BF1 | 91.85,105.92 91.85,135.99 v91.44,136.4 | 91.85,105.92 91.85,103.07 101.19,93.73 101.19,70.16 104.44,66.9 104.44,40.08 106.48,40.08 107.7,38.86 107.7,24.23 106.48,23.01 D28.S2 | 91.85,105.92 v92.25,105.92
  Route2 0.203: v82.91,138.43 82.09,137.62 82.09,135.59 68.68,122.17 68.68,118.11 C31.H2 | v177.6,108.36 208.08,138.84 210.11,138.84 239.37,168.1 242.21,168.1 B17.N2
  Route15 0.203: B14.S2 284.07,159.56 284.07,162.41 278.79,167.69 v278.79,168.1 | A13.U1 302.77,221.74 v302.77,216.46 303.17,216.46 310.49,216.46 311.3,215.65 313.74,215.65 314.15,215.24 314.96,215.24 v315.77,214.43 | v389.33,164.44 351.13,202.64 351.13,203.45 349.5,205.08 347.47,205.08 v345.03,207.52 | v80.47,185.98 77.22,185.98 67.06,196.14 66.65,196.14 48.77,214.02 47.55,214.02 37.39,224.18 32.51,224.18 6.5,250.19 2.03,250.19 A36.J2
  Bottom 0.203: 445.41,163.63 445.41,167.28 442.98,167.28 440.13,170.13 v425.09,170.13 | 445.41,163.63 445.41,162.41 B01.R2 | v425.09,227.43 423.06,227.43 422.25,228.24 418.19,228.24 AB04.AS1 | v278.79,168.1 277.57,168.1 275.54,170.13 269.44,170.13 269.04,169.72 244.65,169.72 243.43,168.5 B17.N2 | v273.51,178.66 273.91,178.26 277.17,178.26 B15.K1 | v302.77,216.46 292.61,216.46 292.2,216.05 274.73,216.05 v274.32,216.46 | 445.41,163.63 390.14,163.63 v389.33,164.44 | v345.03,207.52 341.38,211.18 323.9,211.18 320.65,214.43 v315.77,214.43 | v91.44,136.4 89.41,138.43 83.31,138.43 v82.91,138.43 | v80.47,185.98 81.28,186.79 83.72,186.79 AB30.BF1 | v177.6,108.36 175.97,106.73 171.09,106.73 170.69,107.14 167.84,107.14 167.44,106.73 108.51,106.73 106.07,109.17 101.19,109.17 97.54,105.51 95.1,105.51 94.69,105.92 v92.25,105.92
MB08  (via drill 0.61)
  Top 0.203: v65.84,182.73 66.24,182.32 66.24,119.33 v65.84,118.92 | v287.73,166.47 288.95,167.69 288.95,205.89 289.76,206.7 289.76,220.12 288.54,221.34 288.54,229.87 v288.14,230.28 | v419.4,216.86 419.4,224.18 420.22,224.99 AB03.AT2 | v345.03,217.27 343.41,215.65 343.41,207.92 v343.81,207.52 | v300.74,213.61 298.3,216.05 298.3,218.9 295.45,221.74 295.45,226.62 293.83,228.24 293.83,231.09 A13.R2 | v318.62,259.13 318.62,262.38 319.02,262.79 A11.D2
  Route2 0.203: v318.62,259.13 295.45,235.97 295.45,235.15 294.64,234.34 294.64,232.72 294.23,232.31 A13.R2 | v141.83,123.39 156.46,138.02 158.09,138.02 v179.63,159.56
  Bottom 0.203: 65.84,119.33 120.29,119.33 121.51,120.55 C27.F1 122.73,120.95 123.95,122.17 126.8,122.17 127.2,122.58 141.02,122.58 v141.83,123.39 | 65.84,119.33 59.33,119.33 59.33,114.86 C32.J1 | v65.84,182.73 79.65,182.73 80.47,183.54 AB30.BH2 | 65.84,119.33 v65.84,118.92 | A11.D2 319.84,263.2 321.46,261.57 323.9,261.57 324.71,260.76 327.96,260.76 A11.E1 | v287.73,166.47 260.1,166.47 259.28,165.66 B16.P2 258.06,164.85 255.22,164.85 253.59,163.22 197.92,163.22 195.07,160.38 180.44,160.38 v179.63,159.56 | v288.14,230.28 289.36,231.5 293.01,231.5 A13.R2 | v419.4,216.86 419,217.27 374.7,217.27 374.29,217.68 360.07,217.68 359.66,217.27 v345.03,217.27 | v343.81,207.52 343.41,207.11 314.15,207.11 313.74,206.7 310.9,206.7 307.64,209.96 304.39,209.96 v300.74,213.61
MB08\  (via drill 0.61)
  Top 0.203: v121.92,118.92 121.11,119.74 121.11,131.93 121.92,132.74 C27.B1 122.73,133.96 123.95,135.18 123.95,167.28 v126.39,169.72 | v69.9,114.86 69.9,121.77 70.31,122.17 70.31,185.98 71.12,186.79 AB31.BF1 71.53,188.01 72.75,189.23 72.75,219.71 70.31,222.15 70.31,245.31 71.12,246.13 v71.12,248.56 | v423.88,205.89 423.88,221.74 AB03.AU2 | v295.45,248.56 295.45,243.28 296.67,242.06 A13.M2 | v275.54,157.12 275.95,157.53 275.95,179.07 274.73,180.29 B15.J1 | v278.38,249.38 276.35,249.38 276.35,198.17 277.17,197.36 B15.C1
  Route2 0.203: v126.39,169.72 149.96,193.29 153.21,193.29 B24.D2 154.43,194.11 154.43,196.14 v205.23,246.94 | B15.C1 277.57,196.14 277.57,193.7 270.66,186.79 269.85,186.79 262.53,179.48 260.5,179.48 259.28,178.26 B16.K2
  Route15 0.203: v411.28,205.89 411.28,206.3 v386.49,231.09 | v345.03,233.53 344.63,233.53 332.44,245.72 330.81,245.72 329.18,247.34 A11.K1
  Bottom 0.203: 69.9,116.08 77.62,116.08 80.47,118.92 v121.92,118.92 | 69.9,116.08 67.46,116.08 65.84,114.45 C31.J2 | v69.9,114.86 69.9,116.08 | v71.12,248.56 70.71,248.97 67.46,248.97 67.06,248.56 62.99,248.56 62.59,248.97 6.1,248.97 5.28,248.16 A36.K2 | B01.S2 449.48,159.56 449.48,163.63 449.88,163.63 453.95,167.69 453.95,205.89 v423.88,205.89 423.47,205.89 v411.28,205.89 | A11.K1 327.96,247.75 325.93,247.75 324.71,248.97 295.86,248.97 v295.45,248.56 295.05,248.56 294.64,248.97 278.79,248.97 v278.38,249.38 278.38,248.97 207.26,248.97 v205.23,246.94 | B16.K2 259.28,178.26 260.5,179.48 270.66,179.48 271.88,180.7 273.91,180.7 B15.J1 | v275.54,157.12 279.2,157.12 280.42,155.91 B14.T2 | v386.49,231.09 385.67,230.28 362.1,230.28 358.85,233.53 v345.03,233.53
MB09  (via drill 0.61)
  Top 0.203: v320.24,261.57 320.24,252.22 319.43,251.41 A11.J2 | v358.04,273.76 351.94,279.86 328.78,279.86 328.78,273.76 A11.A1 | AB03.AS2 423.47,227.84 422.66,227.03 422.66,218.08 v423.06,217.68 423.06,217.27 v423.06,212.8 | v126.39,144.12 126.39,142.09 126.8,141.68 126.8,135.99 123.95,133.15 123.95,119.33 125.17,118.11 C27.H1 | B16.R2 255.22,161.19 254.41,160.38 v254.41,144.93 254.41,144.53 254.41,139.24 v254.81,138.84 | v301.95,120.55 301.55,120.95 301.55,138.02 v300.74,138.84 | v360.07,24.23 356.01,28.3 v356.01,78.69 | v441.76,214.02 441.76,142.9 441.35,142.49 441.35,114.86 v442.57,113.64
  Route2 0.203: v320.24,261.57 320.24,261.98 323.9,265.63 323.9,266.45 326.75,269.29 326.75,271.32 327.96,272.54 A11.A1 | v453.14,79.5 447.85,79.5 445.01,76.66 445.01,66.09 429.97,51.05 429.97,50.24 421.03,41.3 421.03,40.49 409.65,29.11 409.65,27.08 408.43,25.86 D04.R2
  Route15 0.203: v423.06,217.68 418.59,217.68 399.49,236.78 398.68,236.78 392.58,242.88 392.18,242.88 391.77,243.28 391.77,244.5 386.89,249.38 382.02,249.38 358.04,273.36 v358.04,273.76 | v356.01,78.69 356.01,79.91 344.22,91.69 343.81,91.69 331.62,103.89 331.62,104.29 323.9,112.01 323.9,113.64 319.84,117.7 319.84,118.11 v316.18,121.77 | v442.57,113.64 453.95,102.26 453.95,85.19 455.98,83.16 455.98,82.35 v453.14,79.5
  Bottom 0.203: v126.39,144.12 126.8,143.71 128.02,143.71 128.83,142.9 207.67,142.9 208.48,143.71 238.15,143.71 239.37,144.93 v254.41,144.93 | v301.95,120.55 305.61,120.55 C12.F2 306.83,121.36 307.64,122.17 315.77,122.17 v316.18,121.77 | v300.74,138.84 288.95,138.84 288.14,139.65 261.72,139.65 260.91,138.84 v254.81,138.84 | v360.07,24.23 402.34,24.23 403.15,25.04 407.21,25.04 D04.R2 | v423.06,212.8 423.47,213.21 440.94,213.21 v441.76,214.02
MB09\  (via drill 0.61)
  Top 0.203: v254.81,182.73 254.41,182.32 254.41,180.29 254.81,179.88 254.81,175.01 B16.L2 | v423.06,236.37 426.31,239.62 426.31,242.88 426.72,243.28 428.75,243.28 428.75,229.87 429.56,229.06 AB03.AS1 | v451.51,203.05 453.95,200.61 453.95,128.27 453.14,127.46 C01.D1 | v292.61,212.39 292.61,213.61 v297.49,218.49
  Route2 0.203: v280.42,208.74 254.81,183.13 v254.81,182.73 | v297.49,218.49 297.49,218.9 303.58,224.99 303.58,226.21 v315.37,238
  Route15 0.203: v173.94,176.63 160.53,190.04 160.53,192.89 B24.D1 | v385.67,237.59 v387.71,235.56 | v451.51,203.05 449.88,204.67 447.45,204.67 445.41,206.7 445.41,209.14 434.44,220.12 434.44,222.15 432,224.59 432,226.21 430.38,227.84 AB03.AS1
  Bottom 0.203: v173.94,176.63 189.79,176.63 195.48,182.32 254.41,182.32 v254.81,182.73 | 327.96,239.62 327.96,238.81 330.4,238.81 331.22,239.62 345.44,239.62 347.07,238 349.1,238 350.32,236.78 358.85,236.78 361.7,239.62 378.76,239.62 379.17,240.03 379.98,240.03 380.39,239.62 383.64,239.62 v385.67,237.59 | 327.96,239.62 327.96,240.84 A11.M1 | v387.71,235.56 388.11,235.97 390.96,235.97 391.36,236.37 399.9,236.37 400.3,235.97 403.56,235.97 403.96,236.37 408.03,236.37 408.43,235.97 410.06,235.97 410.46,236.37 v423.06,236.37 | v280.42,208.74 284.07,212.39 v292.61,212.39 | v315.37,238 316.99,239.62 327.96,239.62
MB10  (via drill 0.61)
  Top 0.203: 328.37,270.92 328.37,267.26 A11.C1 | 328.37,270.92 328.37,271.32 324.71,271.32 323.9,270.51 323.9,266.45 319.43,261.98 319.43,257.91 A11.F2 | v425.09,256.29 425.09,250.6 434.85,240.84 434.85,227.43 433.63,226.21 AB02.AT2 | v330.4,279.04 330,278.64 330,272.54 328.37,270.92 | v127.2,142.49 127.2,107.14 125.58,105.51 C27.M1 | v259.69,142.9 260.1,143.31 260.1,156.72 258.88,157.94 B16.S2 | v253.19,220.12 251.16,218.08 251.16,192.89 250.75,192.48 250.75,184.76 v250.34,184.35
  Route2 0.203: v347.07,62.43 350.72,66.09 353.57,66.09 D09.A1 | v286.92,253.03 286.11,253.03 v253.19,220.12
  Route15 0.203: v401.52,279.86 v425.09,256.29 | D09.A1 354.38,66.09 354.38,63.65 363.32,54.71 363.32,53.09 364.95,51.46 364.95,49.84 363.73,48.62 366.17,46.18 374.29,46.18 374.7,45.77 377.55,45.77 390.55,32.77 391.36,32.77 392.18,31.95 392.99,31.95 407.21,17.73 409.25,17.73 417.78,26.26 408.03,36.02 408.03,37.64 D04.L2 | v347.07,62.43 347.07,62.84 345.03,64.87 340.97,64.87 323.09,82.75 322.27,82.75 v306.02,99.01 | v290.58,100.23 290.58,100.63 v248.31,142.9 | v236.12,185.17 236.12,183.54 243.03,176.63 243.03,176.22 243.43,175.82 243.84,175.82 247.5,172.16 247.5,168.1 254.81,160.78 256.44,160.78 258.06,159.16 B16.S2
  Bottom 0.203: v401.52,279.86 401.12,279.45 388.93,279.45 388.11,278.64 387.3,278.64 385.27,280.67 365.35,280.67 364.13,279.45 360.07,279.45 359.26,280.26 331.62,280.26 v330.4,279.04 | v127.2,142.49 127.61,142.09 208.48,142.09 208.89,142.49 248.31,142.49 | 248.31,142.49 259.28,142.49 v259.69,142.9 | v306.02,99.01 305.21,99.82 301.95,99.82 301.55,99.42 297.89,99.42 297.49,99.82 290.98,99.82 v290.58,100.23 | 248.31,142.49 v248.31,142.9 | v286.92,253.03 287.32,252.63 299.52,252.63 302.77,255.88 317.81,255.88 318.62,256.69 A11.F2 | v250.34,184.35 249.12,185.57 236.53,185.57 v236.12,185.17
MB10\  (via drill 0.61)
  Top 0.203: v272.69,87.63 273.1,88.04 v273.1,142.9 | v261.31,142.9 260.5,143.71 260.5,166.06 259.28,167.28 259.28,170.94 B16.M2 258.88,172.16 260.1,173.38 260.1,199.8 v259.69,200.2
  Route2 0.203: A11.L2 319.84,244.5 321.06,244.5 326.75,250.19 326.75,251.82 328.37,253.44 A11.H1 | v297.49,243.28 296.67,243.28 273.51,220.12 273.51,217.27 272.29,216.05 272.29,214.43 271.48,213.61 271.48,211.99 v259.69,200.2 | v435.25,220.52 436.07,221.34 436.07,221.74 AB02.AU2
  Route15 0.203: C01.K1 455.17,111.61 455.17,114.05 453.54,115.67 453.54,117.7 451.1,120.14 451.1,139.65 453.95,142.49 453.95,212.8 451.51,215.24 450.7,215.24 450.29,215.65 445.41,215.65 440.54,220.52 438.91,220.52 437.29,222.15 AB02.AU2 | v402.74,221.34 402.74,221.74 v372.67,251.82
  Bottom 0.203: B24.M2 157.68,170.94 158.5,170.13 256.85,170.13 258.06,171.35 B16.M2 | v272.69,87.63 275.13,87.63 275.54,88.04 280.01,88.04 280.42,88.44 C14.T2 | v261.31,142.9 v273.1,142.9 | v297.49,243.28 297.89,242.88 317.4,242.88 318.62,244.09 A11.L2 | v435.25,220.52 418.19,220.52 417.78,220.93 412.9,220.93 412.5,220.52 403.56,220.52 v402.74,221.34 | v372.67,251.82 368.61,255.88 347.88,255.88 345.44,258.32 330,258.32 328.37,256.69 328.37,254.66 A11.H1
MB11  (via drill 0.61)
  Top 0.203: v311.3,281.08 311.3,256.69 311.71,256.29 311.71,252.22 312.52,251.41 A12.J1 | v425.5,276.61 425.91,276.2 425.91,254.25 435.25,244.91 435.25,229.87 436.07,229.06 AB02.AS2 436.88,227.84 437.69,227.03 437.69,202.23 437.29,201.83 437.29,200.2 437.69,199.8 437.69,146.96 440.94,143.71 440.94,114.05 v441.35,113.64 | v398.68,51.87 401.12,49.43 403.15,49.43 v403.15,70.97 | v240.59,156.72 241,157.12 241,198.17 238.56,200.61 238.56,263.6 v239.37,264.41
  Route2 0.203: v194.26,96.16 195.07,96.16 234.49,135.59 234.49,136.4 251.97,153.87 253.19,153.87 254.81,155.5 B16.T2 | v441.35,113.64 v404.77,77.06
  Route15 0.203: v239.37,264.41 239.78,264.41 245.06,259.13 256.03,259.13 v262.94,252.22
  Bottom 0.203: v194.26,96.16 193.85,96.57 161.75,96.57 158.5,99.82 123.95,99.82 122.73,101.04 C27.N1 | v311.3,281.08 311.71,281.48 326.75,281.48 327.96,280.26 329.59,280.26 330.4,281.08 360.07,281.08 360.88,280.26 363.32,280.26 364.54,281.48 386.49,281.48 387.71,280.26 390.14,280.26 390.55,280.67 421.44,280.67 v425.5,276.61 | v398.68,51.87 399.08,52.27 405.99,52.27 407.21,51.05 D04.F2 | v403.15,70.97 403.15,76.66 404.37,76.66 v404.77,77.06 | v240.59,156.72 254,156.72 254.81,155.91 B16.T2 | v262.94,252.22 284.07,252.22 286.92,249.38 308.86,249.38 310.08,250.6 312.12,250.6 A12.J1
MB11\  (via drill 0.61)
  Top 0.203: v164.59,160.78 165,161.19 165,178.26 164.19,179.07 160.53,179.07 160.53,175.41 B24.L1 | v284.07,90.47 284.07,86.41 C14.U2 | v348.69,105.92 349.1,105.51 349.1,92.51 352.35,89.26 352.35,79.91 351.94,79.5 351.94,64.87 351.13,64.06 D09.B1 | v451.51,221.34 451.1,220.93 451.1,215.65 453.54,213.21 453.54,206.3 450.7,203.45 v450.7,142.09 | v449.48,107.95 449.48,105.51 C01.M2 | v334.06,109.58 334.87,108.76 334.87,105.51 C10.M2
  Route2 0.203: v284.07,90.47 284.48,90.47 285.29,91.29 285.29,96.57 287.32,98.6 287.32,99.42 307.64,119.74 307.64,122.17 308.86,123.39 C12.E2 | v286.92,147.37 287.32,147.78 288.14,147.78 288.54,148.18 288.54,148.59 290.98,151.03 291.39,151.03 308.05,167.69 308.05,172.16 315.77,179.88 316.59,179.88 316.99,180.29 316.99,180.7 320.65,184.35 320.65,185.57 323.9,188.82 323.9,190.04 328.37,194.51 328.37,196.14 B11.C1
  Route15 0.203: v286.92,147.37 286.92,144.12 305.21,125.83 307.24,125.83 308.86,124.21 C12.E2 310.08,123.39 310.08,121.36 v322.27,109.17 | v252.37,166.88 252.78,166.88 266.6,153.06 266.6,150.62 v267,150.22 | v451.51,221.34 450.7,222.15 450.7,222.96 445.41,228.24 443.38,228.24 AB02.AS1 | v445.82,118.92 444.6,117.7 447.45,114.86 447.45,109.98 v449.48,107.95
  Bottom 0.203: v164.59,160.78 180.44,160.78 186.13,166.47 211.33,166.47 212.55,167.69 214.17,167.69 214.99,166.88 243.43,166.88 244.25,167.69 245.87,167.69 246.69,166.88 v252.37,166.88 253.59,166.88 254.81,168.1 B16.N2 | v267,150.22 267.41,150.62 283.26,150.62 286.51,147.37 v286.92,147.37 | C10.M2 335.69,105.1 336.09,105.51 340.16,105.51 340.56,105.92 v348.69,105.92 349.1,105.92 447.85,105.92 448.67,105.1 C01.M2 | v450.7,142.09 453.95,138.84 453.95,118.92 v445.82,118.92 | v322.27,109.17 322.68,109.58 v334.06,109.58
MB_LOAD  (via drill 0.61)
  Top 0.203: v380.8,166.06 381.2,166.47 381.2,230.28 379.98,231.5 379.98,232.72 379.17,233.53 376.73,233.53 376.73,232.31 AB07.AR1
  Bottom 0.203: 412.9,233.12 413.71,232.31 AB04.AR1 | 412.9,233.12 403.56,233.12 402.34,231.9 AB05.AR1 401.12,231.9 399.9,231.9 398.68,233.12 390.96,233.12 389.74,231.9 AB06.AR1 388.52,232.31 388.11,232.72 383.64,232.72 383.24,233.12 380.39,233.12 379.17,231.9 376.73,231.9 AB07.AR1 | 425.09,233.12 426.31,231.9 AB03.AR1 | 412.9,233.12 425.09,233.12 | 425.09,233.12 438.51,233.12 439.32,232.31 AB02.AR1 | v380.8,166.06 380.39,166.47 361.7,166.47 360.88,165.66 B08.P2
MB_PARITY_ODD  (via drill 0.61)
